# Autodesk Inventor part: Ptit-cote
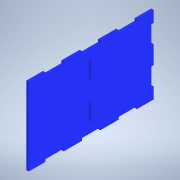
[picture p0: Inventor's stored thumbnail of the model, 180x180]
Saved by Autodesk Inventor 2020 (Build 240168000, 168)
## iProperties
Created: 2023-12
Part Number: Ptit-cote
Material: Générique
Document SubType Name: Modeling
Designer: bruno
Density: 1 g/cm^3
Appearance: Bleu - Peinture murale - Brillant
Author: bruno
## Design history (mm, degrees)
sketch "Esquisse1"
  geometry: L1 (59.938, 165)-(82.812, 165); L2 (59.938, 162)-(59.938, 165); L3 (37.062, 162)-(59.938, 162); L4 (37.062, 165)-(37.062, 162); L5 (14.188, 165)-(37.062, 165); L6 (14.188, 162)-(14.188, 165); L7 (0, 162)-(14.188, 162); L8 (82.812, 165)-(82.812, 162); L9 (0, 182.812)-(0, 162); L10 (97, 318)-(0, 318); L11 (97, 297.188)-(97, 318); L12 (94, 297.188)-(97, 297.188); L13 (94, 274.312)-(94, 297.188); L14 (97, 274.312)-(94, 274.312); L15 (97, 251.438)-(97, 274.312); L16 (94, 251.438)-(97, 251.438); L17 (94, 228.563)-(94, 251.438); L18 (97, 228.563)-(94, 228.563); L19 (97, 205.688)-(97, 228.563); L20 (94, 205.688)-(97, 205.688); L21 (94, 182.812)-(94, 205.688); L22 (3, 205.688)-(3, 182.812); L23 (0, 205.688)-(3, 205.688); L24 (0, 228.563)-(0, 205.688); L25 (3, 228.563)-(0, 228.563); L26 (3, 182.812)-(0, 182.812); L27 (0, 318)-(0, 297.188); L28 (3, 251.438)-(3, 228.563); L29 (0, 251.438)-(3, 251.438); L30 (0, 274.312)-(0, 251.438); L31 (3, 274.312)-(0, 274.312); L32 (3, 297.188)-(3, 274.312); L33 (0, 297.188)-(3, 297.188); L34 (97, 182.812)-(94, 182.812); L35 (97, 162)-(97, 182.812); L36 (82.812, 162)-(97, 162); L37 (337, 82.938)-(337, 105.812); L38 (243, 60.063)-(240, 60.063); L39 (243, 82.938)-(243, 60.063); L40 (240, 82.938)-(243, 82.938); L41 (240, 105.812)-(240, 82.938); L42 (243, 105.812)-(240, 105.812); L43 (243, 137)-(243, 105.812); L44 (337, 105.812)-(334, 105.812); L45 (334, 105.812)-(334, 128.688); L46 (334, 128.688)-(334, 137); L47 (334, 137)-(322.812, 137); L48 (322.812, 137)-(322.812, 140); L49 (322.812, 140)-(299.938, 140); L50 (299.938, 140)-(299.938, 137); L51 (299.938, 137)-(277.062, 137); L52 (277.062, 137)-(277.062, 140); L53 (277.062, 140)-(254.188, 140); L54 (254.188, 140)-(254.188, 137); L55 (254.188, 137)-(243, 137); L56 (254.188, 6)-(254.188, 3); L57 (243, 6)-(254.188, 6); L58 (243, 14.313)-(243, 6); L59 (243, 37.188)-(243, 14.313); L60 (240, 37.188)-(243, 37.188); L61 (240, 60.063)-(240, 37.188); L62 (277.062, 3)-(277.062, 6); L63 (277.062, 6)-(299.938, 6); L64 (299.938, 6)-(299.938, 3)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; 112 further points
  constraints: 368 end point
extrude "Extrusion3" new body sketch "Esquisse1" distance "d4" = 3; taper "d5" = 0 deg
sketch "Esquisse2"
  geometry: L1 (-243, 82.812)-(-243, 59.938) reference; L2 (-240, 82.812)-(-240, 59.938) reference; L3 (-243, 82.812)-(-240, 82.812) reference; L4 (-243, 59.938)-(-240, 59.938) reference; L5 (-243, 37.063)-(-240, 37.063) reference; L6 (-240, 37.063)-(-240, 14.188) reference; L7 (-243, 37.063)-(-243, 14.188) reference; L8 (-243, 14.188)-(-240, 14.188) reference; 1 further point
extrude "Extrusion4" cut sketch "Esquisse2" distance "d6" = 3; taper "d7" = 0 deg
node "Solide3"
node "Référence1"
node "Référence2"
node "Référence3"
node "Référence4"
node "Référence5"
node "Référence6"
node "Référence7"
node "Référence8"
